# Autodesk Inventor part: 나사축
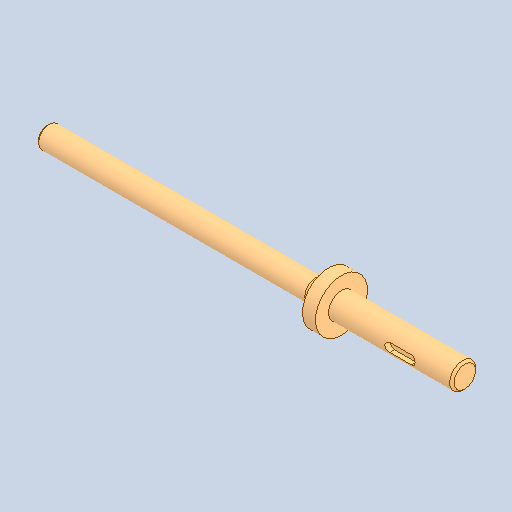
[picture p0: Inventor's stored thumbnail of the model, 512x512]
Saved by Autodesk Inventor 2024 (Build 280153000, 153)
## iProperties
Created: 2024-08
Part Number: 나사축
Material: 강철, 연강
Document SubType Name: Modeling
Designer: user
Density: 7.86 g/cm^3
Appearance: 기본값
Author: jhkim
Sending System: Autodesk Inventor 2025
Preprocessor: ST-DEVELOPER v20
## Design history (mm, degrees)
feature "솔리드1"
node "솔리드2"
